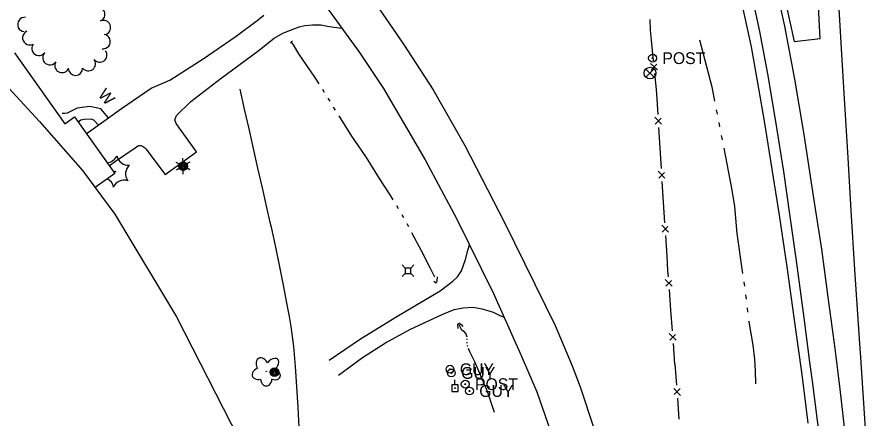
# Model space of a CAD drawing. Extents: x 589250 to 1188077, y 162953 to 363065.
# Drawn here: x 593601.3 to 594036.1, y 173250.4 to 173455.3 of the extents above; entities that cross this region are included whole.
import ezdxf

# ---------------------------------------------------------------- set-up
doc = ezdxf.new("R2010")
doc.units = 0
for name, color, linetype in [('E_BLD', 7, 'Continuous'), ('E_DRN', 7, 'Continuous'), ('E_DRN_DrainTile', 7, 'Continuous'), ('E_DWY', 7, 'Continuous'), ('E_FEN_P', 7, 'Continuous'), ('E_LAND_TreeLine_P', 7, 'Continuous'), ('E_LAND_Vegetation', 7, 'Continuous'), ('E_LTG', 7, 'Continuous'), ('E_MAP_Limits', 7, 'Continuous'), ('E_MISCPROP', 7, 'Continuous'), ('E_PATH_Sidewalk', 7, 'Continuous'), ('E_RDWY', 7, 'Continuous'), ('E_RDWY_Gravel', 7, 'Continuous'), ('E_SIG', 7, 'Continuous'), ('E_STRUCT', 7, 'Continuous'), ('E_UTL_AG_Bold', 7, 'Continuous'), ('E_UTL_EGuyWire', 7, 'Continuous'), ('E_UTL_EPowerPole', 7, 'Continuous'), ('E_WAL', 7, 'Continuous'), ('E_WAL_Text', 7, 'Continuous'), ('E_WTR_FlowLine', 7, 'Continuous')]:
    doc.layers.add(name, color=color, linetype=linetype)

msp = doc.modelspace()

# ---------------------------------------------------------------- linework, layer by layer
at = {"layer": 'E_BLD'}
for p, q in [((593599.91, 173437.13), (593625.65, 173400.87)), ((593625.65, 173400.87), (593630.61, 173404.39)), ((593630.61, 173404.39), (593651.13, 173375.48)), ((593651.13, 173375.48), (593641.12, 173368.37))]:
    msp.add_line(p, q, dxfattribs=at)
at = {"layer": 'E_DRN'}
for centre, radius, start, end in [((593741.51, 173442.13), 0.679, 80.322, 186.5822), ((593814.7, 173320.61), 0.752, 251.5017, 357.7619), ((593826.73, 173298.22), 0.84, 67.5565, 173.8167)]:
    msp.add_arc(centre, radius, start, end, dxfattribs=at)
at = {"layer": 'E_DRN_DrainTile'}
msp.add_lwpolyline([(593714.8, 173418.46), (593717.09, 173408.41), (593719.37, 173398.36), (593721.65, 173388.31), (593723.94, 173378.26), (593726.22, 173368.21), (593728.51, 173358.16), (593730.04, 173351.41), (593730.78, 173348.11), (593732.97, 173338.03), (593735.05, 173327.94), (593737.05, 173317.83), (593738.99, 173307.71), (593739.94, 173302.65), (593740.82, 173297.57), (593742.17, 173287.36), (593743.11, 173277.09), (593743.79, 173266.79), (593744.34, 173256.46), (593744.93, 173246.14)], dxfattribs=at)
at = {"layer": 'E_DWY'}
for p, q in [((593724.39, 173454.03), (593727.06, 173456.28)), ((593712.92, 173445.63), (593724.39, 173454.03)), ((593745.07, 173450.37), (593748.06, 173450.92)), ((593748.06, 173450.92), (593751.96, 173451.28)), ((593751.96, 173451.28), (593753.16, 173451.4)), ((593753.16, 173451.4), (593756.17, 173451.25)), ((593756.17, 173451.25), (593759.48, 173450.6)), ((593732.36, 173444.45), (593736.72, 173447.03)), ((593736.72, 173447.03), (593740.6, 173448.59)), ((593740.6, 173448.59), (593745.07, 173450.37)), ((593759.48, 173450.6), (593762.79, 173450.16)), ((593762.79, 173450.16), (593766.82, 173449.7)), ((593696.09, 173434.05), (593712.92, 173445.63)), ((593723.96, 173437.91), (593732.36, 173444.45)), ((593705.26, 173424.09), (593723.96, 173437.91)), ((593679.16, 173423.16), (593696.09, 173434.05)), ((593669.61, 173419.1), (593679.16, 173423.16)), ((593689.85, 173412.22), (593705.26, 173424.09)), ((593654.57, 173408.64), (593669.61, 173419.1)), ((593682.56, 173405.1), (593689.85, 173412.22)), ((593638.84, 173397.47), (593654.57, 173408.64)), ((593681.69, 173402.88), (593682.56, 173405.1)), ((593682.42, 173400.99), (593681.69, 173402.88)), ((593692.77, 173386.55), (593682.42, 173400.99)), ((593636.61, 173395.94), (593638.84, 173397.47)), ((593662.79, 173389.66), (593663.39, 173389.87)), ((593663.39, 173389.87), (593664.29, 173389.78)), ((593651.51, 173381.76), (593661.41, 173388.63)), ((593661.41, 173388.63), (593662.79, 173389.66)), ((593664.29, 173389.78), (593665.2, 173389.4)), ((593665.2, 173389.4), (593666.31, 173388.81)), ((593666.31, 173388.81), (593667.02, 173388.03)), ((593667.02, 173388.03), (593669.48, 173384.66)), ((593676.74, 173375.07), (593692.77, 173386.55)), ((593648.3, 173379.46), (593651.51, 173381.76)), ((593669.48, 173384.66), (593676.74, 173375.07)), ((593831.29, 173336.89), (593831.89, 173339.23)), ((593829.85, 173331.73), (593831.29, 173336.89)), ((593827.85, 173325.99), (593829.85, 173331.73)), ((593825.81, 173322.92), (593827.85, 173325.99)), ((593816.99, 173315.74), (593823.38, 173320.6)), ((593823.38, 173320.6), (593825.81, 173322.92)), ((593794.96, 173302.63), (593816.99, 173315.74)), ((593828.74, 173306.99), (593833.67, 173307.45)), ((593833.67, 173307.45), (593838.44, 173306.58)), ((593801.53, 173296.08), (593818.33, 173303.78)), ((593818.33, 173303.78), (593824.19, 173306.16)), ((593824.19, 173306.16), (593828.74, 173306.99)), ((593838.44, 173306.58), (593843.99, 173304.77)), ((593843.99, 173304.77), (593847.44, 173303.11)), ((593847.44, 173303.11), (593849.56, 173302.29)), ((593776.32, 173291.3), (593794.96, 173302.63)), ((593789.09, 173289.22), (593801.53, 173296.08)), ((593760.33, 173280.38), (593776.32, 173291.3)), ((593777.42, 173281.8), (593789.09, 173289.22)), ((593765.21, 173272.67), (593777.42, 173281.8))]:
    msp.add_line(p, q, dxfattribs=at)
at = {"layer": 'E_FEN_P'}
for p, q in [((593924.31, 173448.62), (593924.03, 173454.06)), ((593924.81, 173443.55), (593924.31, 173448.62)), ((593925.83, 173433.06), (593924.81, 173443.55)), ((593927.78, 173428.33), (593924.24, 173431.67)), ((593924.58, 173428.18), (593927.43, 173431.24)), ((593927.27, 173418.3), (593926.47, 173426.57)), ((593927.42, 173416.07), (593927.27, 173418.3)), ((593928.09, 173405.56), (593927.42, 173416.07)), ((593929.87, 173400.76), (593926.45, 173404.22)), ((593926.67, 173400.72), (593929.62, 173403.68)), ((593929.17, 173388.53), (593928.5, 173399.05)), ((593929.85, 173378.01), (593929.17, 173388.53)), ((593931.63, 173373.21), (593928.21, 173376.67)), ((593928.43, 173373.18), (593931.38, 173376.13)), ((593930.93, 173360.98), (593930.26, 173371.5)), ((593931.6, 173350.47), (593930.93, 173360.98)), ((593933.39, 173345.67), (593929.97, 173349.13)), ((593930.19, 173345.63), (593933.14, 173348.59)), ((593932.69, 173333.44), (593932.02, 173343.95)), ((593933.17, 173325.93), (593932.69, 173333.44)), ((593933.39, 173322.92), (593933.17, 173325.93)), ((593935.23, 173318.14), (593931.77, 173321.57)), ((593932.03, 173318.07), (593934.94, 173321.06)), ((593934.65, 173305.91), (593933.87, 173316.42)), ((593935.43, 173295.4), (593934.65, 173305.91)), ((593937.26, 173290.62), (593933.8, 173294.04)), ((593934.06, 173290.55), (593936.98, 173293.53)), ((593936.69, 173278.38), (593935.91, 173288.89)), ((593936.69, 173278.38), (593937.48, 173267.66)), ((593936.1, 173265.9), (593939.63, 173262.41)), ((593939.37, 173265.97), (593936.39, 173262.93)), ((593937.97, 173261.03), (593938.77, 173250.31))]:
    msp.add_line(p, q, dxfattribs=at)
at = {"layer": 'E_LAND_TreeLine_P'}
for centre, start, end in [((593642.41, 173456.65), 293.4211, 113.4211), ((593605.22, 173451.52), 84.2318, 264.2318), ((593645.32, 173449.93), 293.4211, 113.4211), ((593607.72, 173444.72), 112.7431, 292.7431), ((593645.12, 173442.79), 262.061, 82.061), ((593612.47, 173439.3), 144.9143, 324.9143), ((593643.44, 173435.94), 217.0999, 37.0999), ((593617.99, 173434.58), 142.2819, 322.2819), ((593637.6, 173431.53), 217.0999, 37.0999), ((593624.13, 173430.61), 147.9178, 327.9178), ((593631.03, 173429.24), 180.9417, 0.9417)]:
    msp.add_arc(centre, 3.66, start, end, dxfattribs=at)
at = {"layer": 'E_LAND_Vegetation'}
for centre, radius in [((593651.27, 173376.58), 0.167), ((593728.37, 173274.67), 0.128)]:
    msp.add_circle(centre, radius, dxfattribs=at)
for centre, radius, start, end in [((593646.68, 173386.88), 5.9, 275.1076, 336.9179), ((593657.9, 173385.72), 5.91, 191.1928, 276.8689), ((593662.49, 173375.41), 5.9, 131.153, 216.9179), ((593644.7, 173367.5), 5.9, 11.1484, 63.5355), ((593655.87, 173366.29), 5.9, 71.153, 156.9179)]:
    msp.add_arc(centre, radius, start, end, dxfattribs=at)
for centre, major_axis, ratio in [((593726.41, 173277.61), (2.11, -3.66), 0.691916), ((593730.93, 173277.33), (-3.15, -3.56), 0.560249), ((593724.67, 173273.43), (3.47, 1.01), 0.782863), ((593732.07, 173273.12), (-3.42, 1.21), 0.716896), ((593728.33, 173270.69), (0.03, 3.45), 0.832022)]:
    msp.add_ellipse(centre, major_axis=major_axis, ratio=ratio, start_param=1.570796, end_param=4.712389, dxfattribs=at)
at = {"layer": 'E_LTG'}
for p, q in [((593684.61, 173380.01), (593682.42, 173381.22)), ((593685.89, 173380.78), (593685.85, 173383.28)), ((593689.35, 173381.34), (593687.2, 173380.05)), ((593684.63, 173378.51), (593682.49, 173377.22)), ((593685.98, 173375.28), (593685.94, 173377.78)), ((593689.41, 173377.34), (593687.23, 173378.55))]:
    msp.add_line(p, q, dxfattribs=at)
for radius in [1.5, 0.125]:
    msp.add_circle((593685.92, 173379.28), radius, dxfattribs=at)
at = {"layer": 'E_MAP_Limits'}
for p, q in [((593564.52, 173454.14), (593612.71, 173402.13)), ((593612.71, 173402.13), (593634.66, 173377.12)), ((593634.66, 173377.12), (593651.14, 173354.82)), ((593651.14, 173354.82), (593682.47, 173302.41)), ((593682.47, 173302.41), (593718.83, 173231.78))]:
    msp.add_line(p, q, dxfattribs=at)
at = {"layer": 'E_MISCPROP'}
for centre, radius in [((593925.31, 173434.34), 2), ((593925.31, 173434.34), 0.25), ((593685.92, 173379.28), 2.23), ((593685.92, 173379.28), 1.67), ((593685.92, 173379.28), 1.12), ((593685.92, 173379.28), 0.558), ((593732.52, 173274.24), 2.23), ((593732.52, 173274.24), 1.67), ((593732.52, 173274.24), 1.12), ((593732.52, 173274.24), 0.558), ((593829.79, 173268.14), 2), ((593829.79, 173268.14), 0.25)]:
    msp.add_circle(centre, radius, dxfattribs=at)
at = {"layer": 'E_PATH_Sidewalk'}
for p, q in [((593635.54, 173403.07), (593633.79, 173402.69)), ((593638.86, 173403.3), (593635.54, 173403.07)), ((593640.45, 173402.8), (593638.86, 173403.3)), ((593633.79, 173402.69), (593632.47, 173401.78)), ((593642.71, 173400.22), (593640.45, 173402.8))]:
    msp.add_line(p, q, dxfattribs=at)
at = {"layer": 'E_RDWY'}
for p, q in [((593987.14, 173475.62), (593992.66, 173450.62)), ((594021.83, 173436.33), (594019.9, 173470.32)), ((593782.11, 173465.04), (593798.26, 173441.48)), ((593975.95, 173465.94), (593979.79, 173447.99)), ((593758.71, 173460.8), (593775.91, 173437.26)), ((593979.79, 173447.99), (593983.98, 173426.37)), ((593992.66, 173450.62), (593997.64, 173423.61)), ((593798.26, 173441.48), (593813.36, 173418.26)), ((593775.91, 173437.26), (593788.12, 173418.9)), ((594023.02, 173416.42), (594021.83, 173436.33)), ((593983.98, 173426.37), (593988.06, 173402.04)), ((593997.64, 173423.61), (594002.36, 173395.47)), ((593788.12, 173418.9), (593809.39, 173382.46)), ((593813.36, 173418.26), (593829.59, 173389.8)), ((594025.11, 173383.47), (594023.02, 173416.42)), ((593988.06, 173402.04), (593992.03, 173376.58)), ((594002.36, 173395.47), (594007.43, 173362.94)), ((593829.59, 173389.8), (593849.85, 173350.55)), ((593809.39, 173382.46), (593825.3, 173352.59)), ((594026.58, 173356.68), (594025.11, 173383.47)), ((593992.03, 173376.58), (593995.24, 173353.67)), ((594007.43, 173362.94), (594011.4, 173336.92)), ((594028.45, 173326.47), (594026.58, 173356.68)), ((593825.3, 173352.59), (593844.14, 173314.37)), ((593995.24, 173353.67), (593998.45, 173331.03)), ((593849.85, 173350.55), (593875.59, 173298.07)), ((594011.4, 173336.92), (594014.64, 173312.44)), ((593998.45, 173331.03), (594002.47, 173301.88)), ((594031.29, 173283.72), (594028.45, 173326.47)), ((593844.14, 173314.37), (593858.33, 173282.72)), ((594014.64, 173312.44), (594018.19, 173286.41)), ((594002.47, 173301.88), (594005.4, 173279.39)), ((593875.59, 173298.07), (593884.33, 173277.54)), ((594018.19, 173286.41), (594020.8, 173265.6)), ((593858.33, 173282.72), (593866.34, 173264.29)), ((594036.15, 173211.79), (594031.26, 173284.27)), ((593884.33, 173277.54), (593888.37, 173266.75)), ((594005.4, 173279.39), (594006.69, 173269.62)), ((594006.69, 173269.62), (594010.82, 173237.02)), ((593866.34, 173264.29), (593877.95, 173230.44)), ((593888.37, 173266.75), (593895.55, 173245.22)), ((594020.8, 173265.6), (594025.84, 173221.3))]:
    msp.add_line(p, q, dxfattribs=at)
at = {"layer": 'E_RDWY_Gravel'}
for p, q in [((593988.21, 173484.33), (593995.36, 173452.79)), ((594010.76, 173444.41), (594009.69, 173463.97)), ((593971.18, 173460.33), (593975.51, 173440.09)), ((593995.36, 173452.79), (593997.52, 173442.82)), ((593997.52, 173442.82), (594010.76, 173444.41)), ((593975.51, 173440.09), (593979.37, 173418.83)), ((593979.37, 173418.83), (593982.24, 173402.26)), ((593982.24, 173402.26), (593986.15, 173377.7)), ((593986.15, 173377.7), (593989.84, 173354.34)), ((593989.84, 173354.34), (593993.77, 173327.98)), ((593993.77, 173327.98), (593998.2, 173296.02)), ((593998.2, 173296.02), (594001.14, 173275.45)), ((594001.14, 173275.45), (594002.07, 173267.56)), ((594002.07, 173267.56), (594004.45, 173248.25))]:
    msp.add_line(p, q, dxfattribs=at)
at = {"layer": 'E_SIG'}
for points in [[(593926.08, 173428.85), (593921.89, 173424.61)], [(593921.89, 173428.81), (593926.12, 173424.58)]]:
    msp.add_lwpolyline(points, dxfattribs=at)
msp.add_circle((593924.02, 173426.73), 3, dxfattribs=at)
at = {"layer": 'E_STRUCT'}
for p, q in [((593814.49, 173319.89), (593813.84, 173320.56)), ((593815.45, 173320.58), (593815.67, 173322.93)), ((593827.04, 173299), (593827.74, 173298.6)), ((593827.74, 173298.6), (593828.58, 173297.51)), ((593825.9, 173298.31), (593826.08, 173296.59))]:
    msp.add_line(p, q, dxfattribs=at)
at = {"layer": 'E_UTL_AG_Bold'}
for points in [[(593799.23, 173327.36), (593797.63, 173328.95)], [(593802.04, 173327.36), (593803.63, 173328.95)], [(593799.23, 173324.55), (593797.63, 173322.95)], [(593802.04, 173324.55), (593803.63, 173322.95)]]:
    msp.add_lwpolyline(points, dxfattribs=at)
msp.add_lwpolyline([(593799.23, 173324.55), (593802.04, 173324.55), (593802.04, 173327.36), (593799.23, 173327.36)], close=True, dxfattribs=at)
at = {"layer": 'E_UTL_EGuyWire'}
for centre, radius in [((593822.03, 173275.76), 2), ((593822.72, 173273.87), 2), ((593822.03, 173275.76), 0.25), ((593822.72, 173273.87), 0.25), ((593831.94, 173264.65), 2), ((593831.94, 173264.65), 0.25)]:
    msp.add_circle(centre, radius, dxfattribs=at)
at = {"layer": 'E_UTL_EPowerPole'}
for points in [[(593824.55, 173267.79), (593824.55, 173270.43)], [(593826.23, 173267.79), (593822.88, 173267.79)], [(593822.88, 173267.79), (593822.88, 173264.43)], [(593822.88, 173264.43), (593826.23, 173264.43)], [(593826.23, 173264.43), (593826.23, 173267.79)]]:
    msp.add_lwpolyline(points, dxfattribs=at)
msp.add_circle((593824.58, 173266.11), 0.217, dxfattribs=at)
at = {"layer": 'E_WAL'}
for p, q in [((593631.89, 173408.79), (593626.73, 173406.32)), ((593638.38, 173409.66), (593631.89, 173408.79)), ((593643.93, 173408.56), (593638.38, 173409.66)), ((593647.84, 173403.86), (593643.93, 173408.56)), ((593625.43, 173406.08), (593624.24, 173406.06)), ((593626.73, 173406.32), (593625.43, 173406.08))]:
    msp.add_line(p, q, dxfattribs=at)
at = {"layer": 'E_WTR_FlowLine'}
for p, q in [((593742.2, 173441.12), (593741.12, 173442.51)), ((593949.3, 173443.74), (593955.57, 173419.71)), ((593745.01, 173436.62), (593742.2, 173441.12)), ((593753.15, 173424.72), (593745.01, 173436.62)), ((593755.26, 173421.33), (593753.15, 173424.72)), ((593758.05, 173416.86), (593757.12, 173418.35)), ((593955.57, 173419.71), (593956.97, 173412.42)), ((593760.83, 173412.38), (593759.9, 173413.87)), ((593763.62, 173407.91), (593762.69, 173409.4)), ((593957.81, 173408.05), (593958.23, 173405.87)), ((593772.04, 173394.49), (593765.49, 173404.93)), ((593959.07, 173401.5), (593959.49, 173399.31)), ((593779.16, 173384.22), (593772.04, 173394.49)), ((593960.34, 173394.94), (593960.76, 173392.76)), ((593961.62, 173388.39), (593965.43, 173368.89)), ((593779.5, 173383.66), (593779.16, 173384.22)), ((593786.11, 173373.01), (593779.5, 173383.66)), ((593791.57, 173364.69), (593786.11, 173373.01)), ((593965.43, 173368.89), (593967.06, 173358.84)), ((593793.09, 173362.11), (593791.57, 173364.69)), ((593795.76, 173357.57), (593794.87, 173359.08)), ((593967.06, 173358.84), (593967.26, 173356.65)), ((593967.26, 173356.65), (593968.34, 173345.02)), ((593798.44, 173353.02), (593797.55, 173354.54)), ((593800.97, 173348.4), (593800.16, 173349.96)), ((593807.45, 173336.1), (593802.61, 173345.29)), ((593968.34, 173345.02), (593971.19, 173324.64)), ((593811.91, 173327.42), (593807.45, 173336.1)), ((593814.21, 173322.61), (593811.91, 173327.42)), ((593971.8, 173320.24), (593972.11, 173318.04)), ((593972.71, 173313.63), (593972.97, 173311.42)), ((593973.49, 173307), (593973.76, 173304.79)), ((593826.46, 173298.58), (593827.78, 173296.21)), ((593974.28, 173300.38), (593974.32, 173300)), ((593974.32, 173300), (593976.41, 173288.08)), ((593827.78, 173296.21), (593828.91, 173295.18)), ((593828.91, 173295.18), (593830.04, 173293.85)), ((593830.04, 173293.85), (593830.65, 173292.34)), ((593830.65, 173292.34), (593830.65, 173292.27)), ((593830.67, 173291.2), (593830.68, 173290.67)), ((593830.65, 173289.61), (593830.63, 173289.08)), ((593830.71, 173288.04), (593830.9, 173287.55)), ((593831.29, 173286.56), (593832, 173284.78)), ((593976.41, 173288.08), (593977.36, 173280.96)), ((593832, 173284.78), (593834.59, 173279.62)), ((593834.59, 173279.62), (593840.94, 173264.62)), ((593977.36, 173280.96), (593977.67, 173274.88)), ((593977.67, 173274.88), (593977.78, 173268.38)), ((593840.94, 173264.62), (593844.59, 173253.84))]:
    msp.add_line(p, q, dxfattribs=at)

# ---------------------------------------------------------------- texts
at = {"layer": 'E_MISCPROP'}
for p in [(593930.31, 173431.34), (593834.79, 173265.14)]:
    msp.add_text('POST', height=6, dxfattribs=at).set_placement(p)
at = {"layer": 'E_UTL_EGuyWire'}
for p in [(593827.03, 173272.76), (593827.72, 173270.87), (593836.94, 173261.65)]:
    msp.add_text('GUY', height=6, dxfattribs=at).set_placement(p)
at = {"layer": 'E_WAL_Text'}
msp.add_text('W', height=6, rotation=312.0686, dxfattribs=at).set_placement((593642.11, 173415.47))

doc.saveas('drawing.dxf')
